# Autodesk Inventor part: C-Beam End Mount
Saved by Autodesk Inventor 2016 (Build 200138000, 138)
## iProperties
Created: 2015-11
Part Number: C-Beam End Mount
Material: Generic
Document SubType Name: Modeling
Designer: John
Density: 1 g/cm^3
Appearance: Default
Author: John
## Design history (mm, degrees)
feature "SOLID1"
body "Solid1"
